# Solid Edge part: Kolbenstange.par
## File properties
Username: bmolnar
Dokumentum tartalom típus: 0
Author: bmolnar
Last saved by: bmolnar
Revision: 94
Sűrűség: 0,000 kg/m^3
Pontosság: 0,990
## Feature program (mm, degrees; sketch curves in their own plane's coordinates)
base feature "unnamed BaseFeature 1"
sketch for "unnamed Protrusion 1" plane through (33.5, 0, 0) normal (1, 0, 0) x-axis (0, 0, 1)
  circle centre (0, 0) radius 40
extrude "unnamed Protrusion 1" add finite 19.5 along +normal
sketch for "Kihúzás_2" plane through (33.5, 0, 0) normal (1, 0, 0) x-axis (0, 0, 1)
  circle centre (0, 0) radius 40
extrude "Kihúzás_2" add finite 4.5 along -normal
sketch for "Furat_1" plane through (-155, 0, 0) normal (-1, 0, 0) x-axis (0, 0, -1)
  hole centre (0, 0) bore radius 5.053
hole "Furat_1" nominal diameter 12 finite  ThreadDepth = 20 mm
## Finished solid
Body 1: solid body, 15 faces, 21 edges, 8 vertices.
  Faces by surface: plane 8, cylinder 4, cone 2, torus 1
  Edges by curve: circle 11, line 6, ellipse 2, intersection 2
Bounding box of the edges (mm; curved faces can reach further): 208.000 x 80.000 x 80.000, from (-155, -40, -40) to (53, 40, 40).
Cylindrical faces by radius (mm): R5.053 x2, R10 x1, R40 x1
Conical faces (half-angle, radius in mm at the cone's reference point): 45 deg R5.553 x1, 59 deg R2.5265 x1
Toroidal faces (ring radius, tube radius in mm): R8.2 r1.8 x1
Planar faces by outward normal: +x 1, +z 1, -x 3, -z 1, oblique 2
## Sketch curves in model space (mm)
circle centre (33.5, 0, 0) radius 40
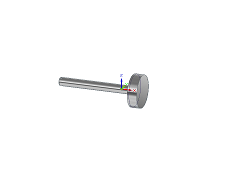
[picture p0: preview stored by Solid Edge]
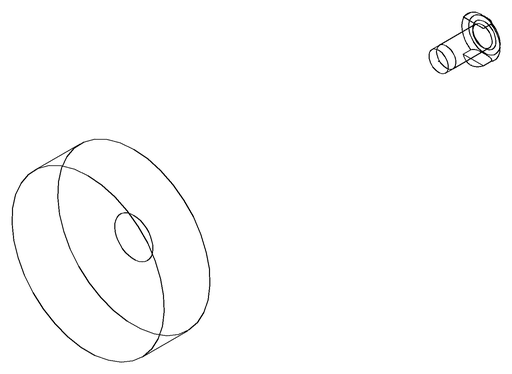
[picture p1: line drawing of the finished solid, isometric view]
